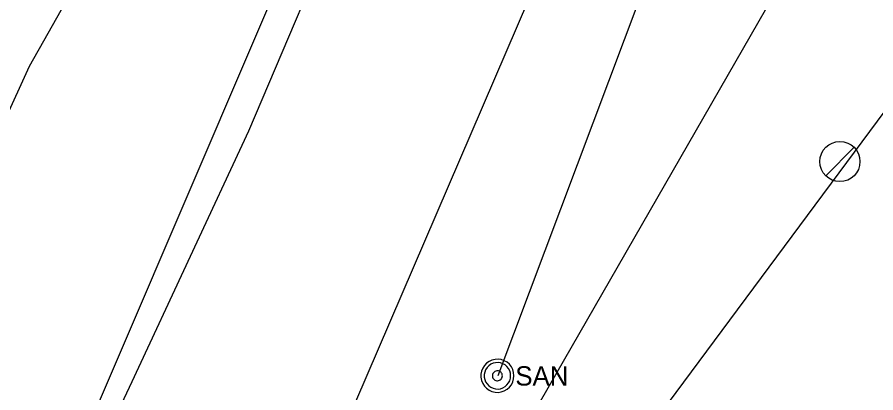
# Model space of a CAD drawing. Extents: x 596028 to 606371, y 330010 to 403088.
# Drawn here: x 604782.6 to 604953.8, y 331091.9 to 331166.7 of the extents above; entities that cross this region are included whole.
import ezdxf

# ---------------------------------------------------------------- set-up
doc = ezdxf.new("R2010")
doc.units = 0
for name, color, linetype in [('E_LTG_CID', 7, 'Continuous'), ('E_UTL_E_UG', 7, 'Continuous'), ('E_UTL_G_UG', 7, 'Continuous'), ('E_UTL_SAN_MH', 7, 'Continuous'), ('E_UTL_SAN_UG', 7, 'Continuous'), ('E_UTL_VLV', 7, 'Continuous'), ('E_UTL_W_UG', 7, 'Continuous')]:
    doc.layers.add(name, color=color, linetype=linetype)

msp = doc.modelspace()

# ---------------------------------------------------------------- linework, layer by layer
at = {"layer": 'E_LTG_CID'}
msp.add_lwpolyline([(604683.3, 330952.09), (604684.22, 330952.88), (604759.72, 331101.53), (604785.03, 331156.95), (604797.91, 331179.74), (604801.59, 331186.25), (604804.8, 331186.14), (604807.66, 331192.41), (604823.38, 331242.67), (604840.85, 331285.28), (604856.87, 331326.77), (604873.94, 331374.12), (604891.84, 331421.7), (604891.8, 331421.71), (604891.79, 331421.76), (604894.68, 331439.03), (604894.44, 331441.88), (604906.75, 331486.37), (604920.4, 331537.51), (604920.44, 331537.44), (604931.69, 331580.97)], dxfattribs=at)
at = {"layer": 'E_UTL_E_UG'}
for points in [[(604870.57, 331033.54), (605033.08, 331252.35), (605033.08, 331392.8), (605061.51, 331399.86), (605069.48, 331571.07), (605141.68, 331571.07)], [(604826.65, 331039.78), (604832.36, 331051.66), (604840.87, 331068.69), (604891.55, 331186.46), (604898.79, 331199.69), (604899.88, 331201.84), (604900.68, 331206.84), (604943.56, 331338.75), (604983.14, 331477.94)], [(604683.3, 330952.09), (604722.4, 330946.58), (604729.82, 330955.05), (604742.66, 330976.26), (604786.15, 331059.02), (604790.11, 331069.45), (604882.51, 331285.09), (604891.05, 331283.2)]]:
    msp.add_lwpolyline(points, dxfattribs=at)
at = {"layer": 'E_UTL_G_UG'}
msp.add_lwpolyline([(604718.21, 330825.28), (604738.73, 330857.66), (604733.36, 330874.38), (604732.32, 330894.54), (604729.33, 330913.4), (604725.16, 330938.36), (604752.74, 330988.13), (604778.16, 331035.55), (604788.31, 331057.65), (604805.53, 331094.16), (604828.8, 331144.07), (604848.89, 331191.36), (604869.57, 331244.15), (604888.61, 331295.88), (604900.58, 331325.56), (604922.44, 331394.24)], dxfattribs=at)
at = {"layer": 'E_UTL_SAN_MH'}
for points in [[(604881.63, 331095.27), (604881.57, 331095.89), (604881.4, 331096.5), (604881.11, 331097.05), (604880.72, 331097.55), (604880.25, 331097.96), (604879.7, 331098.27), (604879.11, 331098.48), (604878.49, 331098.57), (604877.86, 331098.54), (604877.25, 331098.39), (604876.68, 331098.13), (604876.17, 331097.76), (604875.74, 331097.31), (604875.4, 331096.78), (604875.17, 331096.2), (604875.05, 331095.58), (604875.05, 331094.96), (604875.17, 331094.34), (604875.4, 331093.76), (604875.74, 331093.23), (604876.17, 331092.77), (604876.68, 331092.41), (604877.25, 331092.15), (604877.86, 331092), (604878.49, 331091.97), (604879.11, 331092.06), (604879.7, 331092.27), (604880.25, 331092.58), (604880.72, 331092.99), (604881.11, 331093.48), (604881.4, 331094.04), (604881.57, 331094.64), (604881.63, 331095.27)], [(604880.97, 331095.27), (604880.92, 331095.77), (604880.78, 331096.25), (604880.55, 331096.7), (604880.24, 331097.09), (604879.86, 331097.42), (604879.43, 331097.67), (604878.95, 331097.83), (604878.46, 331097.91), (604877.96, 331097.88), (604877.47, 331097.76), (604877.01, 331097.56), (604876.6, 331097.26), (604876.26, 331096.9), (604875.99, 331096.48), (604875.8, 331096.01), (604875.7, 331095.52), (604875.7, 331095.02), (604875.8, 331094.53), (604875.99, 331094.06), (604876.26, 331093.64), (604876.6, 331093.27), (604877.01, 331092.98), (604877.47, 331092.77), (604877.96, 331092.66), (604878.46, 331092.63), (604878.95, 331092.7), (604879.43, 331092.87), (604879.86, 331093.12), (604880.24, 331093.45), (604880.55, 331093.84), (604880.78, 331094.29), (604880.92, 331094.77), (604880.97, 331095.27)], [(604879.32, 331095.27), (604879.3, 331095.46), (604879.25, 331095.64), (604879.16, 331095.8), (604879.05, 331095.95), (604878.91, 331096.08), (604878.74, 331096.17), (604878.57, 331096.23), (604878.38, 331096.26), (604878.19, 331096.25), (604878.01, 331096.2), (604877.84, 331096.13), (604877.68, 331096.02), (604877.55, 331095.88), (604877.45, 331095.72), (604877.38, 331095.55), (604877.35, 331095.36), (604877.35, 331095.17), (604877.38, 331094.99), (604877.45, 331094.82), (604877.55, 331094.66), (604877.68, 331094.52), (604877.84, 331094.41), (604878.01, 331094.33), (604878.19, 331094.29), (604878.38, 331094.28), (604878.57, 331094.31), (604878.74, 331094.37), (604878.91, 331094.46), (604879.05, 331094.59), (604879.16, 331094.73), (604879.25, 331094.9), (604879.3, 331095.08), (604879.32, 331095.27)]]:
    msp.add_lwpolyline(points, dxfattribs=at)
at = {"layer": 'E_UTL_SAN_UG'}
msp.add_line((604878.46, 331095.3), (604991.18, 331395.06), dxfattribs=at)
at = {"layer": 'E_UTL_VLV'}
msp.add_lwpolyline([(604943.79, 331135.11), (604949.45, 331140.77)], dxfattribs=at)
msp.add_circle((604946.62, 331137.94), 4, dxfattribs=at)
at = {"layer": 'E_UTL_W_UG'}
msp.add_lwpolyline([(604662.85, 330776.78), (604719.99, 330861.17), (604771.51, 330900.13), (604792.62, 330926.22), (604804.59, 330947.13), (605054.68, 331381.7), (605055.13, 331442.45), (605044.65, 331474.36), (605047.01, 331851.63), (605038.36, 332278.66), (605035.8, 332410.28), (605072.23, 332411.32), (605076.98, 332411.12), (605079.88, 332411.16)], dxfattribs=at)

# ---------------------------------------------------------------- texts
at = {"layer": 'E_UTL_SAN_MH'}
msp.add_text('SAN', height=3.849, dxfattribs=at).set_placement((604881.9, 331093.32))

doc.saveas('drawing.dxf')
